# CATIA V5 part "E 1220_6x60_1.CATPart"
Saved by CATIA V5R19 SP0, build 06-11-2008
Part number: E 1220_6x60_1
Definition: E 1220_6x60_1
Nomenclature: E 1220_6x60_1
Source: Unknown
Description: PART--DESC
Bounding box of the stored display mesh (mm): x -31 to -19, y -6 to 6, z -49.45 to 10.55
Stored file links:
  C:\Users\jsmid\Desktop\DP_Smidak_Forma LEGO\E 1220_6x60_1.CATPart
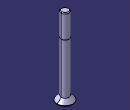
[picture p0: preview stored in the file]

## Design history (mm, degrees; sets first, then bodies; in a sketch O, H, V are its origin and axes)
Body1 "E 1220_6x60" (main body)
  Solid1: solid without history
